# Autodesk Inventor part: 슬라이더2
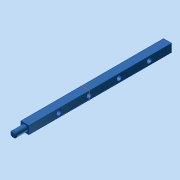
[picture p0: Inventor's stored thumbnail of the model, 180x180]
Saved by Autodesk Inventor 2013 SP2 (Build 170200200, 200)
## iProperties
Company: 한국ATC센터
Created: 2015-04
Part Number: 슬라이더2
Document SubType Name: Modeling
Designer: KYOUNG IL JANG
Density: 7.85 g/cm^3
Material: 강
Author: KYOUNG IL JANG
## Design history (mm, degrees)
sketch "스케치3"
  geometry: L1 (4, 142)-(-4, 142); L2 (-4, 142)-(-4, 0); L3 (-4, 0)-(4, 0); L4 (4, 0)-(4, 142); 3 further points
  constraints: 8 end point, 2 coincident, 2 parallel, 1 horizontal, 1 midpoint, 1 perpendicular
  dimensions: "d5" = 8 distance of L1.start L1.end; "d6" = 142 distance of L1.end L2.end
extrude "돌출3" new body sketch "스케치3" stored distance "d7" = 8; taper "d8" = 0 deg
sketch "스케치4"
  geometry: L1 (8, 0)-(0, 0) reference; 3 further points
  constraints: 1 midpoint, 1 vertical alignment
  dimensions: "d9" = 30 distance of point (4, 30) point (4, 0)
hole "구멍1" sketch "스케치4" at (4, 30) diameter "d10" = 5; stored, may be unused: countersink angle "d14" = 90 deg, drill point angle "d16" = 118 deg; dims "d11" = 6, "d12" = 4, "d13" = 2, "d15" = 8
sketch "스케치5"
  geometry: C1 r 3 at (4, -4); 1 further point
  constraints: 1 centre point, 1 coincident
  dimensions: "d20" = 6 diameter of C1
extrude "돌출4" join sketch "스케치5" distance "d21" = 12; taper "d22" = 0 deg
chamfer "모따기1" distance "d23" = 1; stored, may be unused: second distance "d24" = 2, angle "d25" = 45 deg
node "작업 평면2"
  node "작업축1"
node "솔리드1"
pattern_linear "직사각형 패턴1" dims "d19" = 30
node "솔리드2"
other parameters: "d26" = 0
